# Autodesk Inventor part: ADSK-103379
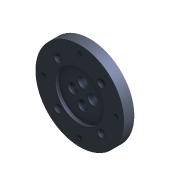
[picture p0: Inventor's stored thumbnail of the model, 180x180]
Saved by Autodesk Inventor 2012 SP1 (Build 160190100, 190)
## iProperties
Shininess: 0.0
Created: 2001-01
Part Number: ADSK-103379
Document SubType Name: Modeling
Stock Number: ADSK-103379
Density: 1 g/cm^3
Material: Default
Density: 0.0
Volumn: 0.0
Area: 0.0
PropertySet Name: Model Information
Control State: 0
Master: False
Checked Out: False
Author: gao
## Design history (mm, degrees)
node "Extrusion1" dims "d1" = 12.7, "d2" = 0
  sketch "Sketch1"
    geometry: C1 r 54.967 at (-1.072, -1.072)
    constraints: 1 centre point
    dimensions: "d0" = 109.93438 diameter of C1
node "Hole1" dims "d4" = 4.9784, "d5" = 9.525, "d6" = 6.35, "d7" = 60 deg, "d8" = 19.05, "d9" = 118 deg, "d42" = 12.7
  sketch "Sketch2" dims "d3" = 89.9922
    geometry: C1 r 54.967 at (0, 0) reference; 2 further points
    constraints: 1 coincident, 1 vertical alignment, 2 other
node "Circular Pattern1" dims "d10" = 40, "d12" = 90 deg
node "Extrusion2" dims "d14" = 12.7, "d15" = 0
  sketch "Sketch3"
    geometry: C1 r 54.967 at (0, 0) reference; C2 r 31.75 at (0, 0)
    constraints: 1 centre point, 1 coincident
    dimensions: "d13" = 63.5 diameter of C2
node "Hole2" dims "d17" = 12.0396, "d18" = 9.525, "d19" = 6.35, "d20" = 60 deg, "d21" = 19.05, "d22" = 118 deg
  sketch "Sketch4" dims "d16" = 24.60625
    geometry: C1 r 31.75 at (0, 0) reference; 2 further points
    constraints: 1 coincident, 1 vertical alignment, 2 other
node "Circular Pattern2" dims "d23" = 40, "d25" = 90 deg
node "Chamfer1" dims "d26" = 1.016, "d27" = 1.016, "d43" = 45 deg
node "Hole3" dims "d30" = 5.334, "d31" = 9.525, "d32" = 6.35, "d33" = 60 deg, "d34" = 19.05, "d35" = 118 deg
  sketch "Sketch5" dims "d28" = 76.2
    geometry: L1 (0, 0)-(49.207, 49.207); L2 (0, 0)-(54.967, 0); 2 further points
    constraints: 4 end point, 1 coincident, 1 horizontal, 1 horizontal alignment, 1 point on line, 4 other
    dimensions: "d29" = 45 deg angle of L1 L2
node "Circular Pattern3" dims "d36" = 40, "d38" = 90 deg
node "Extrusion3" dims "d40" = 3.96875, "d41" = 0
  sketch "Sketch6"
    geometry: C1 r 6.02 at (0, -12.303) reference; C2 r 6.02 at (12.303, 0) reference; C3 r 6.02 at (-12.303, 0) reference; C4 r 6.02 at (0, 12.303) reference; C5 r 54.967 at (0, 0) reference; C6 r 29.997 at (0, 0)
    constraints: 1 centre point, 1 coincident
    dimensions: "d39" = 59.9948 diameter of C6
body "Solid1"
